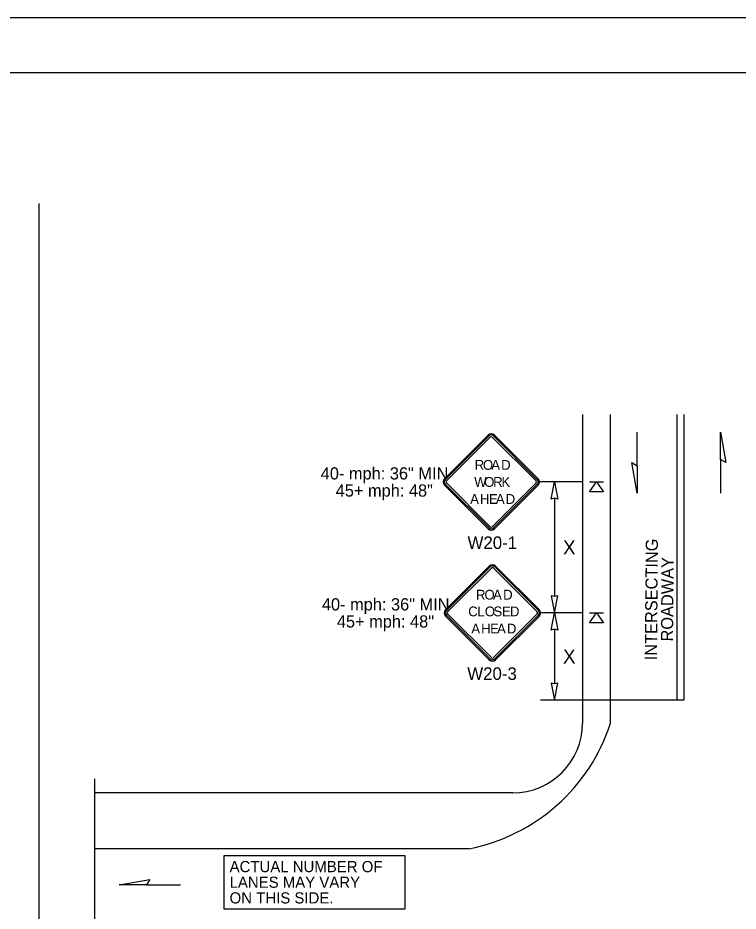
# Model space of a CAD drawing. Extents: x 99958 to 100176, y 99935 to 100011.
# Drawn here: x 100047.76 to 100051.88, y 99975.57 to 99980.69 of the extents above; entities that cross this region are included whole.
import ezdxf

# ---------------------------------------------------------------- set-up
doc = ezdxf.new("R2010")
doc.units = 0
for name, color, linetype in [('RD_ED_ShoulderPavedEdge', 7, 'Continuous'), ('RD_MK_LineDblYellowCenter', 7, 'Continuous'), ('RD_MK_LineEdgeWhite', 7, 'Continuous'), ('RD_MK_LineStop', 7, 'Continuous'), ('SH_DE_DetailBody1Text', 7, 'Continuous'), ('SH_GI_PlotLimits', 7, 'Continuous'), ('SH_GI_SheetBorder', 7, 'Continuous'), ('SH_TI_Tables', 7, 'Continuous'), ('TR_SN_ConstructionSigns', 7, 'Continuous'), ('TR_WZ_PortableSignMountBlk-Org', 7, 'Continuous'), ('TR_WZ_WorkZoneDetails', 7, 'Continuous'), ('TR_WZ_WorkZoneTextCurrent', 7, 'Continuous')]:
    doc.layers.add(name, color=color, linetype=linetype)

msp = doc.modelspace()

# ---------------------------------------------------------------- linework, layer by layer
at = {"layer": 'RD_ED_ShoulderPavedEdge'}
msp.add_line((100050.5869, 99976.2485), (100048.195, 99976.2485), dxfattribs=at)
msp.add_lwpolyline([(100050.9869, 99978.415), (100050.9869, 99976.6485)], dxfattribs=at)
msp.add_arc((100050.5869, 99976.6485), 0.4, 270, 0, dxfattribs=at)
at = {"layer": 'RD_MK_LineDblYellowCenter'}
for p, q in [((100051.5269, 99978.415), (100051.5269, 99976.7784)), ((100051.5669, 99978.415), (100051.5669, 99976.7784))]:
    msp.add_line(p, q, dxfattribs=at)
at = {"layer": 'RD_MK_LineEdgeWhite'}
for p, q in [((100051.1469, 99976.6485), (100051.1469, 99978.415)), ((100050.3369, 99975.9285), (100048.195, 99975.9285))]:
    msp.add_line(p, q, dxfattribs=at)
msp.add_arc((100050.132, 99976.9747), 1.0661, 281.0842, 342.1828, dxfattribs=at)
at = {"layer": 'RD_MK_LineStop'}
msp.add_line((100051.5669, 99976.7784), (100051.1469, 99976.7784), dxfattribs=at)
at = {"layer": 'SH_GI_PlotLimits'}
msp.add_lwpolyline([(100039.0625, 99969.6875), (100056.0625, 99969.6875), (100056.0625, 99980.6875), (100039.0625, 99980.6875)], close=True, dxfattribs=at)
at = {"layer": 'SH_GI_SheetBorder'}
msp.add_line((100040, 99980.375), (100055.75, 99980.375), dxfattribs=at)
at = {"layer": 'SH_TI_Tables'}
msp.add_lwpolyline([(100048.9348, 99975.8901), (100049.9693, 99975.8901), (100049.9693, 99975.5831), (100048.9348, 99975.5831)], close=True, dxfattribs=at)
at = {"layer": 'TR_SN_ConstructionSigns'}
for p, q in [((100050.4465, 99978.2978), (100050.1959, 99978.0472)), ((100050.4515, 99978.2928), (100050.2009, 99978.0422)), ((100050.2078, 99978.0353), (100050.4584, 99978.2858)), ((100050.4703, 99978.2858), (100050.7209, 99978.0353)), ((100050.7279, 99978.0422), (100050.4773, 99978.2928)), ((100050.7329, 99978.0472), (100050.4823, 99978.2978)), ((100050.1959, 99978.0114), (100050.4465, 99977.7608)), ((100050.2009, 99978.0164), (100050.4515, 99977.7658)), ((100050.4584, 99977.7728), (100050.2078, 99978.0233)), ((100050.7209, 99978.0233), (100050.4703, 99977.7728)), ((100050.4773, 99977.7658), (100050.7279, 99978.0164)), ((100050.4823, 99977.7608), (100050.7329, 99978.0114)), ((100050.4532, 99977.5478), (100050.2026, 99977.2972)), ((100050.7395, 99977.2972), (100050.4889, 99977.5478)), ((100050.4581, 99977.5428), (100050.2075, 99977.2922)), ((100050.2145, 99977.2853), (100050.4651, 99977.5358)), ((100050.477, 99977.5358), (100050.7276, 99977.2853)), ((100050.7346, 99977.2922), (100050.484, 99977.5428)), ((100050.2026, 99977.2614), (100050.4532, 99977.0108)), ((100050.2075, 99977.2664), (100050.4581, 99977.0158)), ((100050.4651, 99977.0228), (100050.2145, 99977.2733)), ((100050.7276, 99977.2733), (100050.477, 99977.0228)), ((100050.484, 99977.0158), (100050.7346, 99977.2664)), ((100050.4889, 99977.0108), (100050.7395, 99977.2614))]:
    msp.add_line(p, q, dxfattribs=at)
for centre, radius, start, end in [((100050.4644, 99978.2799), 0.0253, 45, 135), ((100050.4644, 99978.2799), 0.0183, 45, 135), ((100050.4644, 99978.2799), 0.00844, 45, 135), ((100050.2138, 99978.0293), 0.0253, 135, 225), ((100050.2138, 99978.0293), 0.0183, 135, 225), ((100050.2138, 99978.0293), 0.00844, 135, 225), ((100050.715, 99978.0293), 0.00844, 315, 45), ((100050.715, 99978.0293), 0.0183, 315, 45), ((100050.715, 99978.0293), 0.0253, 315, 45), ((100050.4644, 99977.7787), 0.0253, 225, 315), ((100050.4644, 99977.7787), 0.0183, 225, 315), ((100050.4644, 99977.7787), 0.00844, 225, 315), ((100050.471, 99977.5299), 0.0253, 45, 135), ((100050.471, 99977.5299), 0.0183, 45, 135), ((100050.471, 99977.5299), 0.00844, 45, 135), ((100050.2205, 99977.2793), 0.0253, 135, 225), ((100050.2205, 99977.2793), 0.0183, 135, 225), ((100050.7216, 99977.2793), 0.0183, 315, 45), ((100050.7216, 99977.2793), 0.0253, 315, 45), ((100050.2205, 99977.2793), 0.00844, 135, 225), ((100050.7216, 99977.2793), 0.00844, 315, 45), ((100050.471, 99977.0287), 0.0253, 225, 315), ((100050.471, 99977.0287), 0.0183, 225, 315), ((100050.471, 99977.0287), 0.00844, 225, 315)]:
    msp.add_arc(centre, radius, start, end, dxfattribs=at)
at = {"layer": 'TR_WZ_PortableSignMountBlk-Org'}
for p, q in [((100051.0269, 99978.0293), (100051.1069, 99978.0293)), ((100051.0269, 99977.2793), (100051.1069, 99977.2793))]:
    msp.add_line(p, q, dxfattribs=at)
for points in [[(100051.0669, 99978.0293), (100051.1069, 99977.9718), (100051.0269, 99977.9718)], [(100051.0669, 99977.2793), (100051.1069, 99977.2218), (100051.0269, 99977.2218)]]:
    msp.add_lwpolyline(points, close=True, dxfattribs=at)
at = {"layer": 'TR_WZ_WorkZoneDetails'}
for p, q in [((100047.875, 99979.625), (100047.875, 99971.5759)), ((100051.2992, 99978.1221), (100051.2992, 99978.315)), ((100051.7765, 99978.1578), (100051.7765, 99977.9649)), ((100050.9869, 99978.0293), (100050.7403, 99978.0293)), ((100050.8269, 99977.9356), (100050.8269, 99977.373)), ((100050.9869, 99977.2793), (100050.7469, 99977.2793)), ((100050.8269, 99977.1856), (100050.8269, 99976.873)), ((100051.1469, 99976.7793), (100050.7469, 99976.7793)), ((100048.4919, 99975.721), (100048.6848, 99975.721))]:
    msp.add_line(p, q, dxfattribs=at)
for points in [[(100051.7765, 99978.315), (100051.8073, 99978.1399), (100051.7765, 99978.1578)], [(100051.2992, 99977.9649), (100051.2683, 99978.1399), (100051.2992, 99978.1221)], [(100050.8269, 99978.0293), (100050.8462, 99977.931), (100050.8269, 99977.9356), (100050.8077, 99977.931)], [(100050.8269, 99977.2793), (100050.8462, 99977.3776), (100050.8269, 99977.373), (100050.8077, 99977.3776)], [(100050.8269, 99977.2793), (100050.8462, 99977.181), (100050.8269, 99977.1856), (100050.8077, 99977.181)], [(100050.8269, 99976.7793), (100050.8462, 99976.8776), (100050.8269, 99976.873), (100050.8077, 99976.8776)], [(100048.3347, 99975.721), (100048.5097, 99975.7519), (100048.4919, 99975.721)]]:
    msp.add_lwpolyline(points, close=True, dxfattribs=at)
msp.add_lwpolyline([(100048.195, 99973.9924), (100048.195, 99975.083), (100048.115, 99975.083), (100048.275, 99975.2379), (100048.195, 99975.2379), (100048.195, 99976.3285)], dxfattribs=at)

# ---------------------------------------------------------------- texts
at = {"layer": 'SH_DE_DetailBody1Text'}
for s, p in [('INTERSECTING', (100051.4129, 99977.0077)), ('ROADWAY', (100051.5049, 99977.1152))]:
    msp.add_text(s, height=0.07, rotation=89.5374, dxfattribs=at).set_placement(p)
at = {"layer": 'SH_TI_Tables'}
for s, p in [('ACTUAL NUMBER OF', (100048.9668, 99975.794)), ('LANES MAY VARY', (100048.9668, 99975.7045)), ('ON THIS SIDE.', (100048.9668, 99975.6148))]:
    msp.add_text(s, height=0.064, rotation=360, dxfattribs=at).set_placement(p)
at = {"layer": 'TR_SN_ConstructionSigns'}
for s, p in [('R', (100050.3698, 99978.0988)), ('O', (100050.4167, 99978.0988)), ('A', (100050.4642, 99978.0988)), ('D', (100050.5207, 99978.0988)), ('W', (100050.3669, 99978.0012)), ('O', (100050.4238, 99978.0012)), ('R', (100050.4753, 99978.0012)), ('K', (100050.5225, 99978.0012)), ('A', (100050.3434, 99977.9035)), ('H', (100050.3997, 99977.9035)), ('E', (100050.4514, 99977.9035)), ('A', (100050.4908, 99977.9035)), ('D', (100050.5471, 99977.9035)), ('R', (100050.3768, 99977.3552)), ('O', (100050.4255, 99977.3552)), ('A', (100050.4744, 99977.3552)), ('D', (100050.5326, 99977.3552)), ('C', (100050.3325, 99977.2596)), ('L', (100050.3846, 99977.2596)), ('O', (100050.4276, 99977.2596)), ('S', (100050.4769, 99977.2596)), ('E', (100050.5258, 99977.2596)), ('D', (100050.5713, 99977.2596)), ('A', (100050.3501, 99977.1612)), ('H', (100050.4064, 99977.1612)), ('E', (100050.4581, 99977.1612)), ('A', (100050.4975, 99977.1612)), ('D', (100050.5537, 99977.1612))]:
    msp.add_text(s, height=0.0562, dxfattribs=at).set_placement(p)
for s, p in [('W20-1', (100050.3286, 99977.6454)), ('W20-3', (100050.327, 99976.8954))]:
    msp.add_text(s, height=0.072, rotation=360, dxfattribs=at).set_placement(p)
at = {"layer": 'TR_WZ_WorkZoneDetails'}
for s, p in [('40- mph: 36" MIN', (100049.4884, 99978.0433)), ('45+ mph: 48"', (100049.574, 99977.9453)), ('40- mph: 36" MIN', (100049.495, 99977.2933)), ('45+ mph: 48"', (100049.5806, 99977.1953))]:
    msp.add_text(s, height=0.07, dxfattribs=at).set_placement(p)
at = {"layer": 'TR_WZ_WorkZoneTextCurrent'}
for p in [(100050.8752, 99977.6143), (100050.8752, 99976.9893)]:
    msp.add_text('X', height=0.08, dxfattribs=at).set_placement(p)

doc.saveas('drawing.dxf')
